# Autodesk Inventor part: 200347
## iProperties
Created: 2007-10
Part Number: 200347
Document SubType Name: Modeling
Designer: TH
Density: 1.425 g/cm^3
Mass: 22.9703 g
Surface Area: 90.2675 cm^2
Volume: 16.1195 cm^3
Material: Acetal Resin, Black
Description: BALL SCREW SLEEVE
Component Category: Lower Component
Author: TH
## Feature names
1. Extrusion1
2. Extrusion2
3. Chamfer1
4. Chamfer2
5. Chamfer3
6. Chamfer4
7. Chamfer5
8. Chamfer6
9. Hole1
10. Extrusion3
